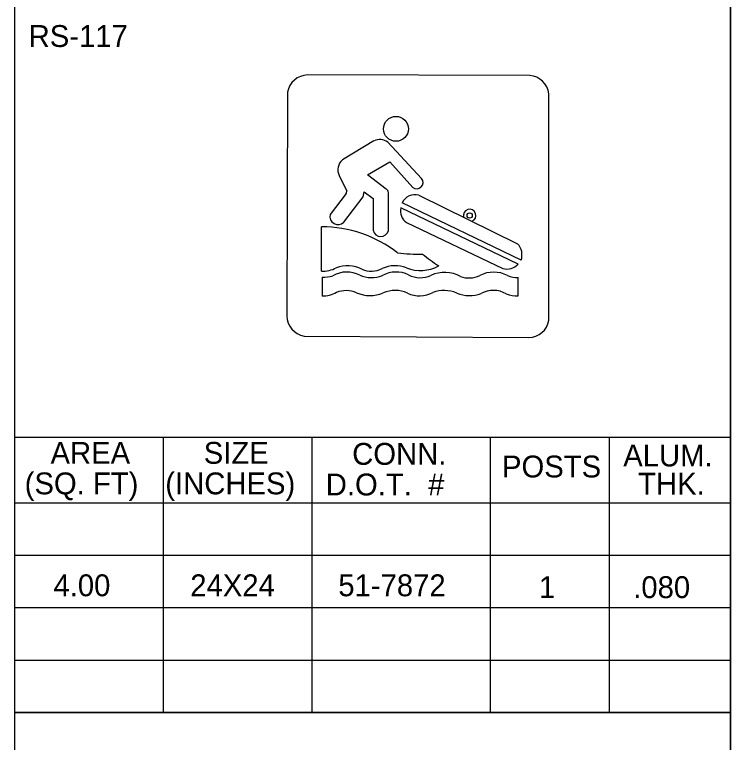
# Model space of a CAD drawing. Extents: x 0 to 2011, y -71 to 1183.
# Drawn here: x 843 to 947.8, y 596.1 to 702.6 of the extents above; entities that cross this region are included whole.
import ezdxf

# ---------------------------------------------------------------- set-up
doc = ezdxf.new("R2010")
doc.units = 0
for name, color, linetype in [('Level 1', 7, 'Continuous'), ('Level 2', 7, 'Continuous'), ('Level 5', 7, 'Continuous')]:
    doc.layers.add(name, color=color, linetype=linetype)

msp = doc.modelspace()

# ---------------------------------------------------------------- linework, layer by layer
at = {"layer": 'Level 1'}
for p, q in [((918.42, 693.65), (885.91, 693.72)), ((882.97, 691.2), (882.88, 658.45)), ((921.23, 657.83), (921.21, 690.95)), ((895.63, 684.08), (891.01, 681.3)), ((902.6, 678.56), (897.67, 683.9)), ((894.7, 679.1), (897.95, 681)), ((897.95, 681), (901.3, 677.26)), ((890.53, 679.02), (891.64, 676.71)), ((897.43, 677.02), (894.7, 679.1)), ((891.54, 676.39), (889.2, 673.31)), ((894.03, 675.91), (894.19, 676.63)), ((894.19, 676.63), (895.49, 675.64)), ((897.74, 670.97), (897.74, 676.5)), ((891.22, 672.17), (894.03, 675.91)), ((895.49, 675.64), (895.49, 671)), ((902.19, 676.14), (916.64, 669.02)), ((916.71, 666.04), (899.55, 674.28)), ((917.15, 666.62), (899.74, 675.03)), ((900.4, 672.12), (914.48, 665.4)), ((887.95, 665.01), (887.95, 671.51)), ((888.04, 664.16), (888.04, 661.38)), ((916.72, 661.43), (916.72, 664.07)), ((885.4, 655.51), (918.29, 655.3))]:
    msp.add_line(p, q, dxfattribs=at)
for centre, radius in [((898.84, 685.84), 1.82), ((909.63, 673.16), 0.388)]:
    msp.add_circle(centre, radius, dxfattribs=at)
for centre, radius, start, end in [((885.99, 690.65), 3.07, 91.4217, 169.7213), ((918.16, 690.59), 3.07, 6.7762, 85.0758), ((896.49, 682.24), 2.03, 54.7138, 114.9884), ((892.24, 679.84), 1.9, 130.1383, 205.8026), ((901.88, 677.99), 0.925, 231.4213, 38.6045), ((891.18, 676.68), 0.464, 320.3528, 2.7928), ((897.06, 676.45), 0.685, 4.1794, 56.7745), ((901.65, 674.08), 2.13, 75.2804, 153.6392), ((901.49, 673.8), 1.99, 165.9996, 237.1134), ((890.38, 673.04), 1.21, 167.4488, 313.5276), ((909.63, 673.16), 0.915, 291.8102, 195.7741), ((887.94, 653.43), 18.09, 51.9517, 89.9696), ((896.62, 671.25), 1.16, 192.8014, 345.8471), ((914.95, 667.41), 2.34, 340.2533, 43.6272), ((902.11, 695.13), 27.62, 263.7046, 271.314), ((919.64, 688.08), 26.61, 230.5979, 236.8698), ((891.76, 661.13), 4.66, 63.3047, 110.7331), ((898.75, 661.34), 4.48, 68.6061, 115.307), ((902.45, 670.57), 5.46, 247.8018, 298.9466), ((915.06, 667.58), 2.26, 254.9343, 316.9219), ((887.98, 669.9), 4.89, 269.5403, 295.7912), ((891.65, 660.79), 4.1, 62.5946, 119.6878), ((895.25, 668.55), 3.53, 246.7794, 296.6399), ((898.87, 660.71), 4.18, 64.0331, 118.8065), ((905.98, 660.07), 4.77, 61.0751, 114.9238), ((913.14, 660.33), 4.54, 63.4348, 116.6721), ((888.31, 668.51), 4.36, 266.3716, 287.4017), ((895.27, 668.59), 4.51, 247.3562, 290.5487), ((902.41, 667.93), 3.87, 243.7182, 293.7613), ((909.53, 667.7), 3.68, 250.233, 295.3184), ((916.61, 667.55), 3.48, 245.5732, 271.8378), ((888.16, 665.29), 3.91, 268.1533, 300.5577), ((891.54, 658.2), 3.97, 67.4011, 110.5147), ((895.07, 666.3), 4.86, 245.7425, 292.8345), ((898.73, 657.81), 4.39, 65.5697, 113.8419), ((902.3, 665.47), 4.07, 244.3278, 298.4907), ((905.9, 657.43), 4.76, 67.1694, 110.3496), ((909.6, 666.05), 4.62, 246.3328, 291.716), ((913.09, 658.34), 3.86, 60.6812, 117.5263), ((916.45, 665.34), 3.92, 248.0149, 273.8925), ((885.95, 658.53), 3.07, 181.4217, 259.7213), ((918.21, 658.37), 3.07, 271.4217, 349.7213)]:
    msp.add_arc(centre, radius, start, end, dxfattribs=at)
at = {"layer": 'Level 2'}
for p, q in [((843.04, 640.71), (947.79, 640.71)), ((864.79, 640.71), (864.79, 600.44)), ((886.54, 640.71), (886.54, 600.44)), ((912.64, 640.71), (912.64, 600.44)), ((930.04, 640.71), (930.04, 600.44)), ((843.04, 631.12), (947.79, 631.12)), ((843.04, 623.45), (947.79, 623.45)), ((843.04, 615.78), (947.79, 615.78)), ((843.04, 608.11), (947.79, 608.11))]:
    msp.add_line(p, q, dxfattribs=at)
for points in [[(947.79, 704.06), (843.04, 704.06), (843.04, 600.44), (947.79, 600.44)], [(947.79, 600.44), (843.04, 600.44), (843.04, 496.81), (947.79, 496.81)]]:
    msp.add_lwpolyline(points, close=True, dxfattribs=at)
at = {"layer": 'Level 5'}
for p, q in [((843.04, 830), (843.04, 600.44)), ((843.04, 830), (843.04, 496.81)), ((947.79, 830), (947.79, 496.81))]:
    msp.add_line(p, q, dxfattribs=at)

# ---------------------------------------------------------------- texts
at = {"layer": 'Level 2'}
for s, p in [('RS-117', (845.1, 697.82)), ('AREA', (848.3, 636.83)), ('SIZE', (870.72, 636.83)), ('CONN.', (892.44, 636.68)), ('ALUM.', (932.1, 636.45)), ('POSTS', (914.36, 634.83)), ('(SQ. FT)', (844.52, 632.36)), ('(INCHES)', (865.09, 632.36)), ('D.O.T.  #', (888.57, 632.2)), ('THK.', (934.28, 632.31))]:
    msp.add_text(s, height=3.2, dxfattribs=at).set_placement(p)
at = {"layer": 'Level 5'}
for s, p in [(' 4.00', (847.54, 617.45)), ('24X24', (868.75, 617.45)), ('51-7872', (890.41, 617.45)), ('1', (919.77, 617.18)), ('.080', (933.56, 617.18))]:
    msp.add_text(s, height=3.2, dxfattribs=at).set_placement(p)

doc.saveas('drawing.dxf')
